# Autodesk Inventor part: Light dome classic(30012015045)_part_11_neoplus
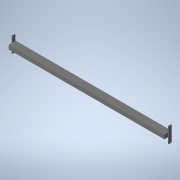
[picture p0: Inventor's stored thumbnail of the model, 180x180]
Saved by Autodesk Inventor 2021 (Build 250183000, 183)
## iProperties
Created: 2026-04
Part Number: Light dome classic(30012015045)_part_11_neoplus
Material: Generic
Catalog Web Link: www.3dfindit.com
Description: Light dome classic_part_11_neoplus-
Vendor: KINGSPAN
Document SubType Name: Modeling
Designer: psAdmin
Manufacturer: KINGSPAN
Mass: 1118.18 g
Surface Area: 1471.78 cm^2
Volume: 1118.18 cm^3
Density: 1 g/cm^3
Appearance: PSOLRGB-255-255-255
Category: PARTsolutions
Company: KINGSPAN
Title: Light dome classic(30012015045)_part_11_neoplus
Author: Cadenas PARTsolutions
PSOL_IDENT_0: {$CADENAS_DATA/23d-libs/kingspan_kla/light_dome_classic_neoplus/parts/part_11.prj},281 {VTYP=3D},{NB=
PSOL_IDENT_1: Light dome classic(30012015045)_part_11_neoplus},{LINA=Light dome classic(30012015045)_part_11_neopl
PSOL_IDENT_2: us},{NN=Light dome classic_part_11_neoplus},{DATE=15.07.2024 10:56:16},{GEOMDATE=01.07.2024 06:37:04
PSOL_IDENT_3: },{VERSION=},{LINEID=10},{WBVAR=LODLEVEL,L,W,DP,OP},{WBNUMERIC=W}  {NB=Light dome classic(3001201504
PSOL_IDENT_4: 5)_part_11_neoplus},{LINA=Light dome classic(30012015045)_part_11_neoplus},{KT=DUMMY},{IDNR=},{PN=Li
PSOL_IDENT_5: ght dome classic},{LODLEVEL=300},{L=120},{W=150},{DRIVE=1},{WX=120,150,180,240,270,300},{DP=4},{OP=5
PSOL_IDENT_6: },{OPX='5','Pneumatic - NRWG F.6 LK'},{LX=1200},{XWX=1500},{VER=2},{DPX='3', 'Fixed','1', 'Natural v
PSOL_IDENT_7: entilation' ,'4','NSHE', '2', 'NSHEV'}
NB: Light dome classic(30012015045)_part_11_neoplus
NN: Light dome classic_part_11_neoplus
NBSYN: $PN.($LODLEVEL.$L.$W.$DP.$OP.)_part_11_neoplus
LINA: Light dome classic(30012015045)_part_11_neoplus
CATALOG: Light + Air
PN: Light dome classic
LODLEVEL: 300
L: 120
W: 150
DP: NSHE
OP: Pneumatic - NRWG F.6 LK
SUPPLIER: KINGSPAN
ARTICLENO: Light dome classic(30012015045)_part_11_neoplus
BOMINFO: Light dome classic(30012015045)_part_11_neoplus
CREATOR: CADENAS GmbH
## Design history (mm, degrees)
sketch "Sketch_1"
  geometry: L1 (12.5, 33)-(-12.5, 33); L2 (-12.5, 33)-(-12.5, -12); L3 (-12.5, -12)-(12.5, -12); L4 (12.5, -12)-(12.5, 33)
  constraints: 8 end point
extrude "Extrusion1" join sketch "Sketch_1" stored distance "d0" = 980; taper "d1" = 0 deg
sketch "Sketch_2"
  geometry: L1 (-36.5, 22)-(-36.5, 2); L2 (-36.5, 2)-(61.5, 2); L3 (61.5, 2)-(61.5, 22); L4 (61.5, 22)-(-36.5, 22)
  constraints: 8 end point
extrude "Extrusion2" join sketch "Sketch_2" distance "d2" = 4; taper "d3" = 0 deg
sketch "Sketch_3"
  geometry: L1 (-36.5, 22)-(-36.5, 2); L2 (-36.5, 2)-(61.5, 2); L3 (61.5, 2)-(61.5, 22); L4 (61.5, 22)-(-36.5, 22)
  constraints: 8 end point
extrude "Extrusion3" join sketch "Sketch_3" distance "d4" = 4; taper "d5" = 0 deg
node "IP_11_XY"
node "IP_11_YZ"
node "IP_11_ZX"
node "IP_11_X"
node "IP_11_Y"
node "IP_11_Z"
node "IP_11_Center"
body "Solid1"
